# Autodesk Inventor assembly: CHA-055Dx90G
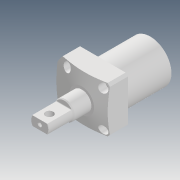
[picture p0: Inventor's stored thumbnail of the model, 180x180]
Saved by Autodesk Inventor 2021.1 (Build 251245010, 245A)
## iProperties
Created: 2019-12
Part Number: CHA-055Dx90G
Description: STEP AP203
Document SubType Name: Assembly
Designer: user
Title: CHA-055Dx90G.STEP
Revision Number: ÈÎºÎ
Sending System: SolidWorks 2017
Preprocessor: SwSTEP 2.0
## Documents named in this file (4)
- D:\Vault_2016\Projekty\Clamptek\Hydraulic\CHA\CHA\CHA-055\Inventor\CHA-055Dx90G\CHA-055Dx90G.iam
- D:\Vault_2016\Projekty\Clamptek\Hydraulic\CHA\CHA\CHA-055\Inventor\CHA-055Dx90G\CHA-055±¾Ìå.ipt
- D:\Vault_2016\Projekty\Clamptek\Hydraulic\CHA\CHA\CHA-055\Inventor\CHA-055Dx90G\CHA-055D»îÈû¸Ë.ipt
- D:\Vault_2016\Projekty\Clamptek\Hydraulic\CHA\CHA\CHA-055\Inventor\CHA-055Dx90G\G1-8¶ÂÍ·.ipt
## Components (4 placed, 4 different names)
1. CHA-055±¾Ìå_1
2. CHA-055D»îÈû¸Ë_2
3. G1-8¶ÂÍ·_3
4. G1-8¶ÂÍ·_4
